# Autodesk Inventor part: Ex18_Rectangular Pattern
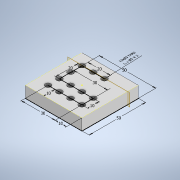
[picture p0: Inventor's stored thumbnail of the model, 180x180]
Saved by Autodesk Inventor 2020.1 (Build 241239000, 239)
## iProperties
Created: 2019-11
Part Number: Ex18_Rectangular Pattern
Material: Generic
Document SubType Name: Modeling
Designer: Synergysoft Dell02
Density: 1 g/cm^3
Appearance: Default
Author: Synergysoft Dell02
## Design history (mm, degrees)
node "Annotations"
  node "Hole Note 1" dims "d0" = 50, "d20" = 10
sketch "Sketch1"
  geometry: L1 (25, 25)-(-25, 25); L2 (-25, 25)-(-25, -25); L3 (-25, -25)-(25, -25); L4 (25, -25)-(25, 25); L5 (25, 25)-(-25, -25); L6 (-25, 25)-(25, -25); 1 further point
  constraints: 12 end point, 2 midpoint, 2 parallel, 1 horizontal, 1 perpendicular
  dimensions: "d0" = 50 distance of L3.end L2.end; "d1" = 50 distance of L2.end L1.end
extrude "Extrusion1" new body sketch "Sketch1" distance "d2" = 10; taper "d3" = 0 deg
sketch "Sketch2"
  geometry: L1 (-15, -15)-(15, -15); L2 (15, -15)-(15, -5); L3 (15, -5)-(-15, -5); L4 (-15, -5)-(-15, 15); L5 (-15, 15)-(5, 15); L6 (-25, -25)-(25, -25) reference; L7 (25, -25)-(25, 25) reference; L8 (-25, 25)-(-25, -25) reference; 1 further point
  constraints: 10 end point, 4 perpendicular, 1 horizontal
  dimensions: "d4" = 10 distance between parallel lines of L6 L1; "d5" = 10 distance of L1.end L2.end; "d6" = 20 distance of L3.end L4.end; "d7" = 20 distance of L4.end L5.end; "d8" = 30 distance of L1.start L1.end; "d9" = 10 distance between parallel lines of L7 L2; "d26" = 30 distance of L2.end L3.end
hole "Hole1" sketch "Sketch2" diameter "d11" = 3; stored, may be unused: countersink angle "d15" = 90 deg, drill point angle "d17" = 118 deg; dims "d12" = 6, "d13" = 5, "d14" = 2, "d16" = 30
pattern_linear "Rectangular Pattern1" dims "d20" = 10, "d23" = 10
pattern_linear "Rectangular Pattern2"
workplane "Work Plane1"
body "Solid1"
other parameters: "d27" = 46.03237 (derived)
